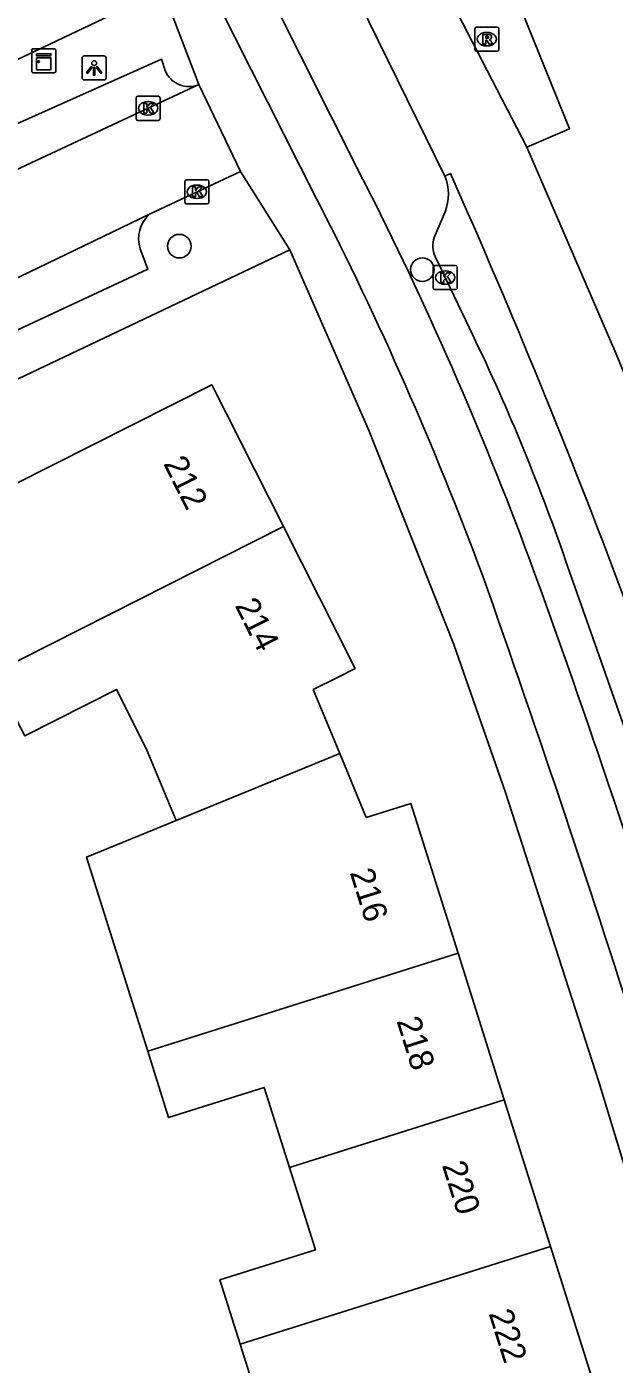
# Model space of a CAD drawing. Extents: x 162250 to 162654, y 380744 to 381605.
# Drawn here: x 162469.2 to 162493.6, y 381328.3 to 381383.7 of the extents above; entities that cross this region are included whole.
import ezdxf

# ---------------------------------------------------------------- set-up
doc = ezdxf.new("R2010")
doc.units = 0
for name, color, linetype in [('IMGEO_Boom', 7, 'Continuous'), ('IMGEO_Fietspad_gesloten', 7, 'Continuous'), ('IMGEO_Kast', 7, 'Continuous'), ('IMGEO_Kolk', 7, 'Continuous'), ('IMGEO_Lichtpunt', 7, 'Continuous'), ('IMGEO_Pand', 7, 'Continuous'), ('IMGEO_Pand_nummerreeks', 7, 'Continuous'), ('IMGEO_Parkeervlak_open', 7, 'Continuous'), ('IMGEO_Rijbaan_lokaal_open', 7, 'Continuous'), ('IMGEO_Rijbaan_regionaal_gesloten', 7, 'Continuous'), ('IMGEO_Rioolput', 7, 'Continuous'), ('IMGEO_Voetpad_open', 7, 'Continuous')]:
    doc.layers.add(name, color=color, linetype=linetype)

msp = doc.modelspace()

# ---------------------------------------------------------------- linework, layer by layer
at = {"layer": 'IMGEO_Boom'}
for centre in [(162475.55, 381374.575), (162485.613, 381373.604)]:
    msp.add_circle(centre, 0.489, dxfattribs=at)
at = {"layer": 'IMGEO_Fietspad_gesloten'}
for points in [[(162477.914, 381387.752), (162483.155, 381377.336)], [(162481.234, 381376.537), (162476.5, 381385.918)]]:
    msp.add_lwpolyline(points, dxfattribs=at)
for centre, radius, start, end in [((162350.169, 381309.633), 149.228, 20.38729, 26.98043), ((162353.437, 381310.904), 143.665, 20.38861, 27.1838), ((162073.679, 381210.088), 443.087, 17.27027, 19.99818), ((161901.418, 381153.183), 622.388, 17.566756, 19.501441)]:
    msp.add_arc(centre, radius, start, end, dxfattribs=at)
at = {"layer": 'IMGEO_Kast'}
for p, q in [((162469.438, 381381.823), (162469.438, 381382.664)), ((162469.438, 381382.664), (162469.438, 381381.823)), ((162469.513, 381382.748), (162470.354, 381382.748)), ((162470.354, 381382.748), (162469.513, 381382.748)), ((162470.438, 381382.673), (162470.438, 381381.832)), ((162470.438, 381381.832), (162470.438, 381382.673)), ((162470.363, 381381.748), (162469.522, 381381.748)), ((162469.522, 381381.748), (162470.363, 381381.748))]:
    msp.add_line(p, q, dxfattribs=at)
for points in [[(162469.633, 381382.538), (162470.233, 381382.538), (162470.233, 381382.453), (162469.633, 381382.453), (162469.633, 381382.538)], [(162469.633, 381382.363), (162470.233, 381382.363), (162470.233, 381381.874), (162469.633, 381381.874), (162469.633, 381382.363)]]:
    msp.add_lwpolyline(points, dxfattribs=at)
msp.add_circle((162469.717, 381382.212), 0.0377, dxfattribs=at)
for centre, start, end in [((162469.516, 381382.67), 92.4484, 184.2845), ((162469.516, 381382.67), 92.4484, 184.2845), ((162470.36, 381382.67), 2.4484, 94.2845), ((162470.36, 381382.67), 2.4484, 94.2845), ((162469.516, 381381.826), 182.4484, 274.2845), ((162469.516, 381381.826), 182.4484, 274.2845), ((162470.36, 381381.826), 272.4484, 4.2845), ((162470.36, 381381.826), 272.4484, 4.2845)]:
    msp.add_arc(centre, 0.0779, start, end, dxfattribs=at)
at = {"layer": 'IMGEO_Kolk'}
for p, q in [((162473.756, 381379.854), (162473.756, 381380.706)), ((162473.831, 381380.78), (162474.683, 381380.78)), ((162474.757, 381380.706), (162474.757, 381379.854)), ((162474.244, 381380.56), (162474.269, 381380.56)), ((162474.683, 381379.78), (162473.831, 381379.78)), ((162474.267, 381380), (162474.242, 381380)), ((162475.851, 381377.325), (162476.703, 381377.325)), ((162475.776, 381376.399), (162475.776, 381377.251)), ((162476.264, 381377.105), (162476.289, 381377.105)), ((162476.777, 381377.251), (162476.777, 381376.399)), ((162476.703, 381376.325), (162475.851, 381376.325)), ((162476.287, 381376.545), (162476.262, 381376.545)), ((162486.059, 381372.85), (162486.059, 381373.702)), ((162486.134, 381373.776), (162486.986, 381373.776)), ((162486.547, 381373.556), (162486.572, 381373.556)), ((162487.06, 381373.702), (162487.06, 381372.85)), ((162486.57, 381372.996), (162486.545, 381372.996)), ((162486.986, 381372.776), (162486.134, 381372.776))]:
    msp.add_line(p, q, dxfattribs=at)
for points in [[(162473.756, 381379.854), (162473.756, 381380.706)], [(162473.831, 381380.78), (162474.683, 381380.78)], [(162474.757, 381380.706), (162474.757, 381379.854)], [(162474.077, 381380.48), (162474.2, 381380.48), (162474.2, 381380.329), (162474.33, 381380.48), (162474.494, 381380.48), (162474.348, 381380.329), (162474.501, 381380.08), (162474.349, 381380.08), (162474.264, 381380.244), (162474.2, 381380.177), (162474.2, 381380.08), (162474.077, 381380.08), (162474.077, 381380.48)], [(162474.683, 381379.78), (162473.831, 381379.78)], [(162475.851, 381377.325), (162476.703, 381377.325)], [(162475.776, 381376.399), (162475.776, 381377.251)], [(162476.097, 381377.025), (162476.22, 381377.025), (162476.22, 381376.874), (162476.35, 381377.025), (162476.514, 381377.025), (162476.368, 381376.874), (162476.521, 381376.625), (162476.369, 381376.625), (162476.284, 381376.789), (162476.22, 381376.722), (162476.22, 381376.625), (162476.097, 381376.625), (162476.097, 381377.025)], [(162476.777, 381377.251), (162476.777, 381376.399)], [(162476.703, 381376.325), (162475.851, 381376.325)], [(162486.059, 381372.85), (162486.059, 381373.702)], [(162486.134, 381373.776), (162486.986, 381373.776)], [(162486.38, 381373.476), (162486.503, 381373.476), (162486.503, 381373.325), (162486.633, 381373.476), (162486.797, 381373.476), (162486.651, 381373.325), (162486.804, 381373.076), (162486.652, 381373.076), (162486.567, 381373.24), (162486.503, 381373.173), (162486.503, 381373.076), (162486.38, 381373.076), (162486.38, 381373.476)], [(162487.06, 381373.702), (162487.06, 381372.85)], [(162486.986, 381372.776), (162486.134, 381372.776)]]:
    msp.add_lwpolyline(points, dxfattribs=at)
for centre, start, end in [((162473.833, 381380.704), 91.552, 178.448), ((162473.833, 381380.704), 91.552, 178.448), ((162474.681, 381380.704), 1.552, 88.448), ((162474.681, 381380.704), 1.552, 88.448), ((162473.833, 381379.856), 181.552, 268.448), ((162473.833, 381379.856), 181.552, 268.448), ((162474.681, 381379.856), 271.552, 358.448), ((162474.681, 381379.856), 271.552, 358.448), ((162475.853, 381377.249), 91.552, 178.448), ((162475.853, 381377.249), 91.552, 178.448), ((162476.701, 381377.249), 1.552, 88.448), ((162476.701, 381377.249), 1.552, 88.448), ((162475.853, 381376.401), 181.552, 268.448), ((162475.853, 381376.401), 181.552, 268.448), ((162476.701, 381376.401), 271.552, 358.448), ((162476.701, 381376.401), 271.552, 358.448), ((162486.136, 381373.7), 91.552, 178.448), ((162486.136, 381373.7), 91.552, 178.448), ((162486.984, 381373.7), 1.552, 88.448), ((162486.984, 381373.7), 1.552, 88.448), ((162486.136, 381372.852), 181.552, 268.448), ((162486.136, 381372.852), 181.552, 268.448), ((162486.984, 381372.852), 271.552, 358.448), ((162486.984, 381372.852), 271.552, 358.448)]:
    msp.add_arc(centre, 0.0765, start, end, dxfattribs=at)
for centre, major_axis, ratio, start_param, end_param in [((162474.243, 381380.28), (-0.387, 0.002), 0.722429, 4.712389, 7.853982), ((162474.268, 381380.28), (-0.39, 0.002), 0.717154, 1.570796, 4.712389), ((162476.263, 381376.825), (-0.387, 0.002), 0.722429, 4.712389, 7.853982), ((162476.288, 381376.825), (-0.39, 0.002), 0.717154, 1.570796, 4.712389), ((162486.546, 381373.276), (-0.387, 0.002), 0.722429, 4.712389, 7.853982), ((162486.571, 381373.276), (-0.39, 0.002), 0.717154, 1.570796, 4.712389)]:
    msp.add_ellipse(centre, major_axis=major_axis, ratio=ratio, start_param=start_param, end_param=end_param, dxfattribs=at)
at = {"layer": 'IMGEO_Lichtpunt'}
for p, q in [((162471.523, 381382.353), (162471.523, 381381.546)), ((162471.523, 381382.353), (162471.523, 381381.546)), ((162472.425, 381382.448), (162471.617, 381382.448)), ((162472.425, 381382.448), (162471.617, 381382.448)), ((162472.519, 381381.546), (162472.519, 381382.353)), ((162472.519, 381381.546), (162472.519, 381382.353)), ((162471.617, 381381.452), (162472.425, 381381.452)), ((162471.617, 381381.452), (162472.425, 381381.452))]:
    msp.add_line(p, q, dxfattribs=at)
for points in [[(162471.897, 381382.017), (162471.936, 381381.989), (162471.748, 381381.727), (162471.71, 381381.754), (162471.897, 381382.017)], [(162471.999, 381381.969), (162472.046, 381381.969), (162472.046, 381381.647), (162471.999, 381381.647), (162471.999, 381381.969)], [(162472.109, 381381.989), (162472.147, 381382.016), (162472.334, 381381.754), (162472.295, 381381.726), (162472.109, 381381.989)]]:
    msp.add_lwpolyline(points, dxfattribs=at)
msp.add_circle((162472.022, 381382.151), 0.0994, dxfattribs=at)
for centre, start, end in [((162471.617, 381382.353), 90, 180), ((162471.617, 381382.353), 90, 180), ((162472.425, 381382.353), 0, 90), ((162472.425, 381382.353), 0, 90), ((162471.617, 381381.546), 180, 270), ((162471.617, 381381.546), 180, 270), ((162472.425, 381381.546), 270, 0), ((162472.425, 381381.546), 270, 360)]:
    msp.add_arc(centre, 0.0946, start, end, dxfattribs=at)
at = {"layer": 'IMGEO_Pand'}
for points in [[(162457.556, 381359.063), (162460.657, 381360.629), (162462.362, 381357.254), (162466.481, 381359.333), (162464.771, 381362.72), (162468.684, 381364.696), (162476.895, 381368.842), (162479.86, 381362.97)], [(162467.843, 381356.9), (162479.86, 381362.97)], [(162479.86, 381362.97), (162482.825, 381357.098), (162482.121, 381356.742), (162481.097, 381356.225), (162482.196, 381353.576)], [(162475.416, 381350.806), (162474.176, 381353.793), (162472.949, 381356.225), (162469.152, 381354.307), (162468.841, 381354.924), (162467.843, 381356.9)], [(162482.196, 381353.576), (162475.416, 381350.806)], [(162482.196, 381353.576), (162483.293, 381350.933), (162484.39, 381351.278), (162485.139, 381351.514), (162487.093, 381345.313)], [(162474.241, 381341.262), (162473.79, 381342.694), (162473.433, 381343.826), (162471.71, 381349.292), (162475.416, 381350.806)], [(162474.241, 381341.262), (162487.093, 381345.313)], [(162487.093, 381345.313), (162489.004, 381339.248)], [(162480.114, 381336.446), (162479.069, 381339.762), (162475.107, 381338.514), (162474.241, 381341.262)], [(162480.114, 381336.446), (162489.004, 381339.248)], [(162489.004, 381339.248), (162490.916, 381333.183)], [(162478.068, 381329.134), (162477.231, 381331.791), (162481.188, 381333.038), (162480.114, 381336.446)], [(162490.916, 381333.183), (162478.068, 381329.134)], [(162490.916, 381333.183), (162492.873, 381326.972), (162490.966, 381326.371), (162492.61, 381321.121)], [(162485.8, 381318.482), (162483.995, 381324.174), (162479.799, 381322.852), (162478.566, 381323.051), (162478.105, 381323.472), (162477.856, 381323.959), (162477.78, 381324.502), (162477.917, 381325.111), (162478.814, 381325.981), (162479.039, 381326.052), (162478.922, 381326.423), (162478.068, 381329.134)]]:
    msp.add_lwpolyline(points, dxfattribs=at)
at = {"layer": 'IMGEO_Parkeervlak_open'}
for points in [[(162486.102, 381374.935), (162486.552, 381375.995)], [(162487.55, 381371.21), (162486.139, 381374.153)], [(162496.62, 381346.611), (162495.413, 381350.353), (162494.184, 381354.055), (162492.758, 381358.137), (162491.545, 381361.568)]]:
    msp.add_lwpolyline(points, dxfattribs=at)
for centre, radius, start, end in [((162484.752, 381376.729), 1.944, 337.8104, 22.4225), ((162487.186, 381374.594), 1.136, 162.5547, 202.8631), ((162408.059, 381332.626), 88.36, 19.12007, 25.89162)]:
    msp.add_arc(centre, radius, start, end, dxfattribs=at)
at = {"layer": 'IMGEO_Rijbaan_lokaal_open'}
for points in [[(162476.356, 381381.26), (162468.565, 381377.619)], [(162478.086, 381377.658), (162476.356, 381381.26)], [(162474.309, 381375.894), (162478.086, 381377.658)], [(162462.791, 381370.36), (162474.309, 381375.894)]]:
    msp.add_lwpolyline(points, dxfattribs=at)
at = {"layer": 'IMGEO_Rijbaan_regionaal_gesloten'}
for points in [[(162486.549, 381377.471), (162481.43, 381387.878)], [(162489.191, 381385.654), (162491.71, 381379.436), (162489.936, 381378.67)], [(162486.855, 381384.614), (162489.936, 381378.67)], [(162489.936, 381378.67), (162493.62, 381370.152), (162498.448, 381358.5), (162502.066, 381347.39)], [(162486.549, 381377.471), (162486.774, 381377.582)]]:
    msp.add_lwpolyline(points, dxfattribs=at)
msp.add_arc((162200.949, 381250.266), 312.898, 17.10917, 24.00969, dxfattribs=at)
at = {"layer": 'IMGEO_Rioolput'}
for p, q in [((162487.784, 381382.715), (162487.784, 381383.567)), ((162487.859, 381383.641), (162488.711, 381383.641)), ((162488.272, 381383.421), (162488.297, 381383.421)), ((162488.785, 381383.567), (162488.785, 381382.715)), ((162488.295, 381382.861), (162488.27, 381382.861)), ((162488.711, 381382.641), (162487.859, 381382.641))]:
    msp.add_line(p, q, dxfattribs=at)
for points in [[(162487.784, 381382.715), (162487.784, 381383.567)], [(162487.859, 381383.641), (162488.711, 381383.641)], [(162488.785, 381383.567), (162488.785, 381382.715)], [(162488.373, 381383.339), (162488.121, 381383.341), (162488.121, 381382.941)], [(162488.121, 381382.941), (162488.245, 381382.941), (162488.245, 381383.103), (162488.256, 381383.103)], [(162488.299, 381383.26), (162488.245, 381383.26), (162488.245, 381383.179)], [(162488.245, 381383.179), (162488.297, 381383.179)], [(162488.303, 381383.074), (162488.374, 381382.941), (162488.514, 381382.941), (162488.449, 381383.067)], [(162488.711, 381382.641), (162487.859, 381382.641)]]:
    msp.add_lwpolyline(points, dxfattribs=at)
for centre, radius, start, end in [((162487.861, 381383.565), 0.0765, 91.552, 178.448), ((162487.861, 381383.565), 0.0765, 91.552, 178.448), ((162488.709, 381383.565), 0.0765, 1.552, 88.448), ((162488.709, 381383.565), 0.0765, 1.552, 88.448), ((162488.255, 381383.05), 0.0533, 26.0293, 88.6989), ((162488.281, 381383.368), 0.19, 274.7715, 282.9687), ((162488.305, 381383.164), 0.0964, 77.0061, 93.1865), ((162488.319, 381383.221), 0.0378, 276.6634, 79.6772), ((162488.372, 381383.229), 0.109, 350.3612, 89.416), ((162488.37, 381383.229), 0.112, 277.5842, 350.9817), ((162488.354, 381383.014), 0.108, 29.5134, 73.7905), ((162487.861, 381382.717), 0.0765, 181.552, 268.448), ((162487.861, 381382.717), 0.0765, 181.552, 268.448), ((162488.709, 381382.717), 0.0765, 271.552, 358.448), ((162488.709, 381382.717), 0.0765, 271.552, 358.448)]:
    msp.add_arc(centre, radius, start, end, dxfattribs=at)
for centre, major_axis, ratio, start_param, end_param in [((162488.271, 381383.141), (-0.387, 0.002), 0.722429, 4.712389, 7.853982), ((162488.296, 381383.141), (-0.39, 0.002), 0.717154, 1.570796, 4.712389)]:
    msp.add_ellipse(centre, major_axis=major_axis, ratio=ratio, start_param=start_param, end_param=end_param, dxfattribs=at)
at = {"layer": 'IMGEO_Voetpad_open'}
for points in [[(162441.657, 381369.405), (162474.869, 381385.175)], [(162474.869, 381385.175), (162476.356, 381381.26)], [(162468.42, 381379.455), (162474.81, 381382.32), (162474.966, 381381.839)], [(162480.129, 381374.422), (162478.086, 381377.658)], [(162456.249, 381363.099), (162480.129, 381374.422)], [(162473.927, 381374.467), (162474.25, 381373.619), (162464.344, 381369.014), (162464.06, 381369.672)], [(162480.129, 381374.422), (162483.417, 381366.917), (162486.919, 381358.092), (162489.061, 381351.971), (162492.918, 381339.992), (162497.897, 381323.608)]]:
    msp.add_lwpolyline(points, dxfattribs=at)
for centre, radius, start, end in [((162475.95, 381382.243), 1.063, 202.3072, 292.4648), ((162475.232, 381374.882), 1.37, 132.3772, 197.65)]:
    msp.add_arc(centre, radius, start, end, dxfattribs=at)

# ---------------------------------------------------------------- texts
at = {"layer": 'IMGEO_Pand_nummerreeks'}
for s, rotation, p in [('212', 296.7913, (162474.869, 381365.579)), ('214', 296.791, (162477.834, 381359.705)), ('216', 287.4922, (162482.6, 381348.655)), ('218', 287.4889, (162484.535, 381342.519)), ('220', 287.4975, (162486.418, 381336.542)), ('222', 287.4865, (162488.351, 381330.409))]:
    msp.add_text(s, height=1, rotation=rotation, dxfattribs=at).set_placement(p)

doc.saveas('drawing.dxf')
